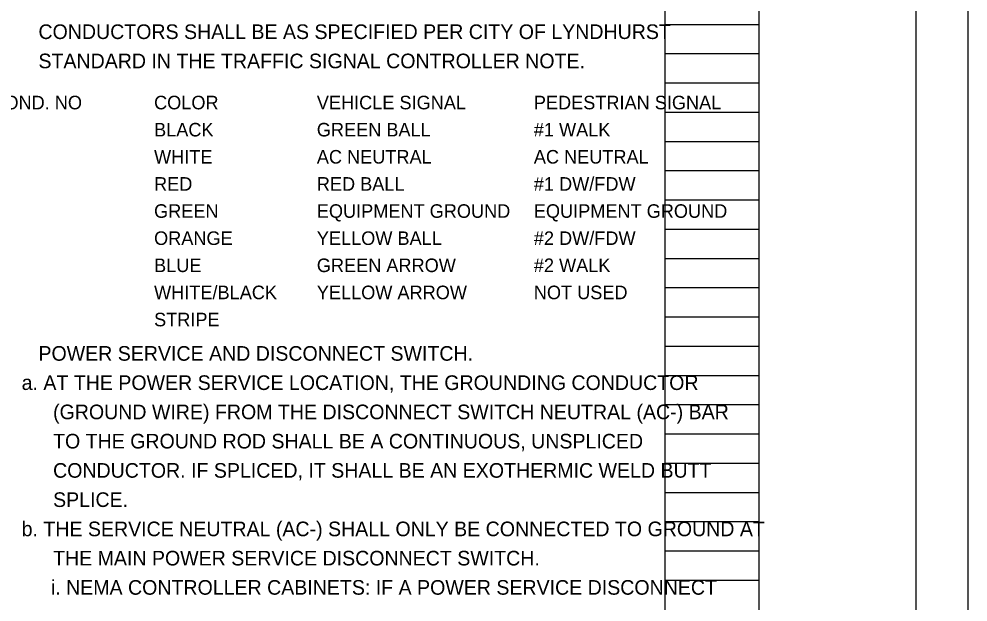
# Model space of a CAD drawing. Extents: x 0 to 34, y -30 to 22.
# Drawn here: x 24.91 to 34, y 5.53 to 11.11 of the extents above; entities that cross this region are included whole.
import ezdxf

# ---------------------------------------------------------------- set-up
doc = ezdxf.new("R2010")
doc.units = 0
for name, color, linetype in [('SH_Border', 7, 'Continuous'), ('SH_Cut_Line', 7, 'Continuous'), ('SH_Data', 7, 'Continuous'), ('SH_Text', 7, 'Continuous')]:
    doc.layers.add(name, color=color, linetype=linetype)

msp = doc.modelspace()

# ---------------------------------------------------------------- linework, layer by layer
at = {"layer": 'SH_Border'}
msp.add_line((32, 0.5), (32, 21.5), dxfattribs=at)
msp.add_lwpolyline([(1.5, 21.5), (33.5, 21.5), (33.5, 0.5), (1.5, 0.5)], close=True, dxfattribs=at)
at = {"layer": 'SH_Cut_Line'}
msp.add_lwpolyline([(0, 0), (34, 0), (34, 22), (0, 22)], close=True, dxfattribs=at)
at = {"layer": 'SH_Data'}
for p, q in [((31.1, 0.98), (31.1, 21.14)), ((32, 0.98), (32, 21.14)), ((31.1, 11.06), (32, 11.06)), ((31.1, 10.78), (32, 10.78)), ((31.1, 10.5), (32, 10.5)), ((31.1, 10.22), (32, 10.22)), ((31.1, 9.94), (32, 9.94)), ((31.1, 9.66), (32, 9.66)), ((31.1, 9.38), (32, 9.38)), ((31.1, 9.1), (32, 9.1)), ((31.1, 8.82), (32, 8.82)), ((31.1, 8.54), (32, 8.54)), ((31.1, 8.26), (32, 8.26)), ((31.1, 7.98), (32, 7.98)), ((31.1, 7.7), (32, 7.7)), ((31.1, 7.42), (32, 7.42)), ((31.1, 7.14), (32, 7.14)), ((31.1, 6.86), (32, 6.86)), ((31.1, 6.58), (32, 6.58)), ((31.1, 6.3), (32, 6.3)), ((31.1, 6.02), (32, 6.02)), ((31.1, 5.74), (32, 5.74))]:
    msp.add_line(p, q, dxfattribs=at)

# ---------------------------------------------------------------- texts
at = {"layer": 'SH_Text'}
for s, height, p in [('CONDUCTORS SHALL BE AS SPECIFIED PER CITY OF LYNDHURST ', 0.14, (25.101, 10.92)), ('STANDARD IN THE TRAFFIC SIGNAL CONTROLLER NOTE. ', 0.14, (25.101, 10.64)), ('COND. NO', 0.12984, (24.6498, 10.2468)), ('COLOR ', 0.12984, (26.2079, 10.2468)), ('VEHICLE SIGNAL', 0.129839, (27.7659, 10.2468)), ('PEDESTRIAN SIGNAL', 0.129839, (29.8434, 10.2468)), ('BLACK ', 0.12984, (26.2079, 9.9871)), ('GREEN BALL ', 0.129839, (27.7659, 9.9871)), ('#1 WALK', 0.12984, (29.8434, 9.9871)), ('WHITE ', 0.12984, (26.2079, 9.7275)), ('AC NEUTRAL', 0.12984, (27.7659, 9.7275)), ('AC NEUTRAL', 0.12984, (29.8434, 9.7275)), ('RED ', 0.12984, (26.2079, 9.4678)), ('RED BALL ', 0.12984, (27.7659, 9.4678)), ('#1 DW/FDW', 0.12984, (29.8434, 9.4678)), ('GREEN ', 0.12984, (26.2079, 9.2081)), ('EQUIPMENT GROUND ', 0.129839, (27.7659, 9.2081)), ('EQUIPMENT GROUND', 0.129839, (29.8434, 9.2081)), ('ORANGE ', 0.12984, (26.2079, 8.9484)), ('YELLOW BALL ', 0.129839, (27.7659, 8.9484)), ('#2 DW/FDW', 0.12984, (29.8434, 8.9484)), ('BLUE ', 0.12984, (26.2079, 8.6887)), ('GREEN ARROW ', 0.129839, (27.7659, 8.6887)), ('#2 WALK', 0.12984, (29.8434, 8.6887)), ('WHITE/BLACK', 0.129839, (26.2079, 8.4291)), ('YELLOW ARROW ', 0.129839, (27.7659, 8.4291)), ('NOT USED', 0.12984, (29.8434, 8.4291)), ('STRIPE', 0.12984, (26.2079, 8.1694)), ('POWER SERVICE AND DISCONNECT SWITCH.', 0.14, (25.101, 7.84)), ('a. AT THE POWER SERVICE LOCATION, THE GROUNDING CONDUCTOR ', 0.14, (24.94, 7.56)), ('(GROUND WIRE) FROM THE DISCONNECT SWITCH NEUTRAL (AC-) BAR ', 0.14, (25.241, 7.28)), ('TO THE GROUND ROD SHALL BE A CONTINUOUS, UNSPLICED ', 0.14, (25.241, 7)), ('CONDUCTOR. IF SPLICED, IT SHALL BE AN EXOTHERMIC WELD BUTT ', 0.14, (25.241, 6.72)), ('SPLICE.', 0.14, (25.241, 6.44)), ('b. THE SERVICE NEUTRAL (AC-) SHALL ONLY BE CONNECTED TO GROUND AT ', 0.14, (24.94, 6.16)), ('THE MAIN POWER SERVICE DISCONNECT SWITCH.', 0.14, (25.241, 5.88)), ('i. NEMA CONTROLLER CABINETS: IF A POWER SERVICE DISCONNECT ', 0.14, (25.22, 5.6))]:
    msp.add_text(s, height=height, dxfattribs=at).set_placement(p)

doc.saveas('drawing.dxf')
